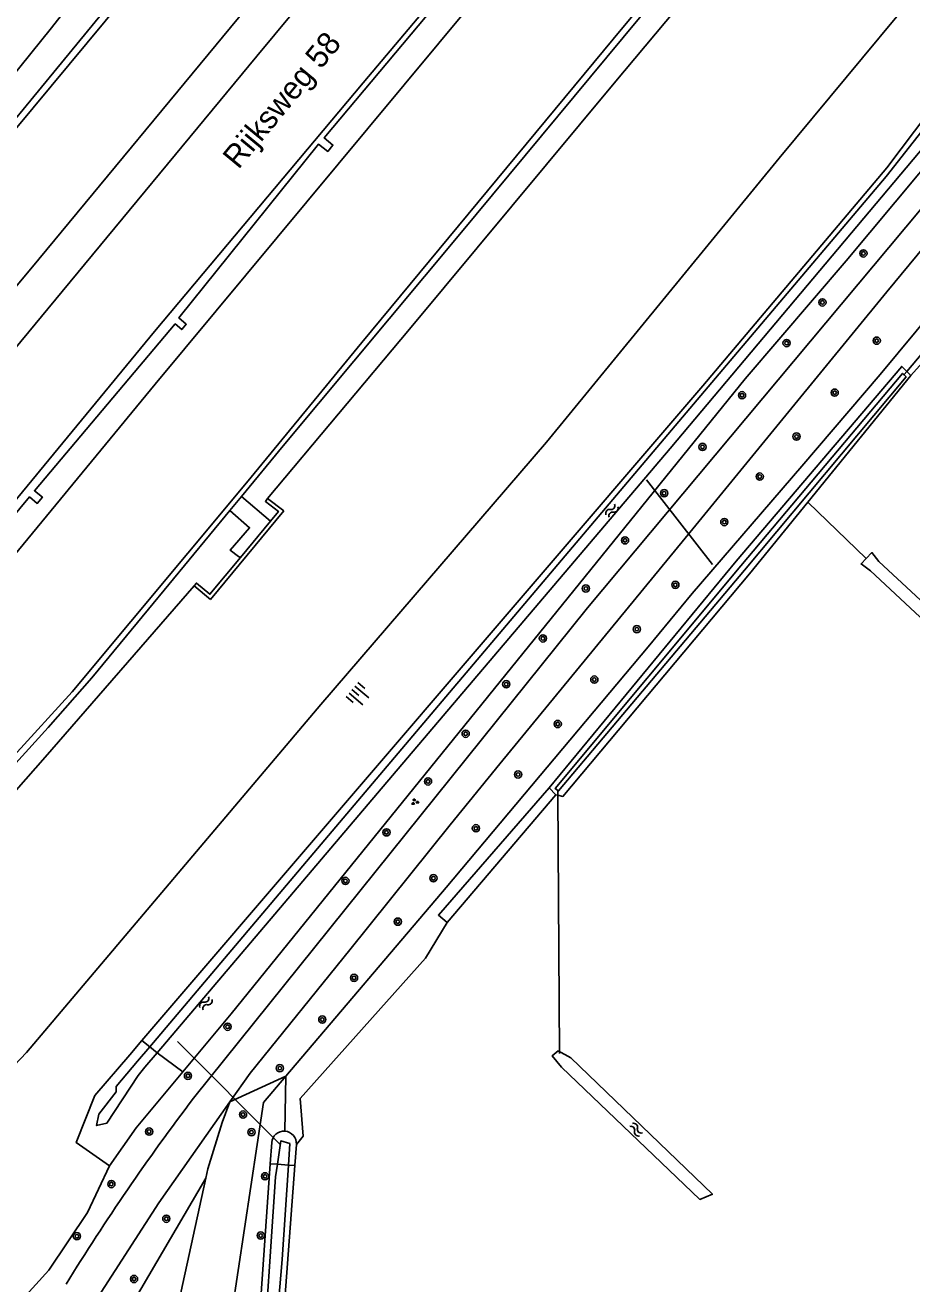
# Model space of a CAD drawing. Extents: x 135990 to 139000, y 393500 to 396000.
# Drawn here: x 136414.3 to 136512.1, y 395330 to 395468.8 of the extents above; entities that cross this region are included whole.
import ezdxf

# ---------------------------------------------------------------- set-up
doc = ezdxf.new("R2010")
doc.units = 0
for name, color, linetype in [('gg-anno-openbare ruimte label', 7, 'Continuous'), ('gg-knt-BGT kruinlijn', 7, 'Continuous'), ('gg-knt-bovenkant onderkant talud', 7, 'Continuous'), ('gg-knt-verharding', 7, 'Continuous'), ('gg-kntw-bovenkant insteek waterloop', 7, 'Continuous'), ('gg-kntw-greppel-droge sloot', 7, 'Continuous'), ('gg-kntw-waterlijn', 7, 'Continuous'), ('gg-kwrk-duiker nz buis', 7, 'Continuous'), ('gt-grn-groengrens', 7, 'Continuous'), ('gt-symb-boom', 7, 'Continuous'), ('gt-symb-groenvak', 7, 'Continuous'), ('gt-symb-talud symbool', 7, 'Continuous'), ('gt-symb-watersymbool', 7, 'Continuous'), ('gx-grn-maaiveld', 7, 'Continuous')]:
    doc.layers.add(name, color=color, linetype=linetype)

# ---------------------------------------------------------------- blocks, each defined once
blk = doc.blocks.new('gt0-BOOM')
at = {"layer": 'gt-symb-boom'}
for radius in [0.4, 0.2]:
    blk.add_circle((0, 0), radius, dxfattribs=at)
blk = doc.blocks.new('gt0-WA')
at = {"layer": 'gt-symb-watersymbool'}
for centre, start, end in [((-0.32, 0.02), 28.0725, 151.9275), ((0.43, 0.42), 208.0725, 331.9275), ((-0.32, -0.43), 28.0725, 151.9275), ((0.43, -0.03), 208.0725, 331.9275)]:
    blk.add_arc(centre, 0.425, start, end, dxfattribs=at)
blk = doc.blocks.new('gt0-GRVAK')
at = {"layer": 'gt-symb-groenvak'}
for p, q in [((-0.11, 0.19), (-0.23, 0.24)), ((-0.18, 0.15), (0.09, 0.15)), ((-0.09, 0.21), (-0.16, 0.32)), ((-0.05, 0.21), (-0.05, 0.39)), ((0, 0.21), (0.06, 0.32)), ((0.01, 0.19), (0.13, 0.24)), ((0.26, -0.05), (0.2, 0.06)), ((0.3, -0.05), (0.3, 0.13)), ((0.35, -0.05), (0.41, 0.06)), ((-0.25, -0.23), (-0.36, -0.18)), ((-0.32, -0.26), (-0.05, -0.26)), ((-0.23, -0.21), (-0.29, -0.09)), ((-0.18, -0.2), (-0.18, -0.02)), ((-0.14, -0.21), (-0.07, -0.09)), ((-0.12, -0.23), (0, -0.18)), ((0.24, -0.07), (0.12, -0.02)), ((0.17, -0.11), (0.44, -0.11)), ((0.37, -0.07), (0.49, -0.02))]:
    blk.add_line(p, q, dxfattribs=at)
blk = doc.blocks.new('gt0-TALUD_1')
at = {"layer": 'gt-symb-talud symbool'}
for p, q in [((-1, -1), (-1, 0)), ((-0.5, -2), (-0.5, 0)), ((0, -1), (0, 0)), ((0.5, -2), (0.5, 0)), ((1, -1), (1, 0))]:
    blk.add_line(p, q, dxfattribs=at)

msp = doc.modelspace()

# ---------------------------------------------------------------- linework, layer by layer
at = {"layer": 'gg-knt-BGT kruinlijn'}
for p, q in [((136503.696, 395491.543), (136479.304, 395462.397)), ((136479.304, 395462.397), (136456.715, 395435.272)), ((136456.715, 395435.272), (136441.073, 395416.607)), ((136441.073, 395416.607), (136442.844, 395415.241)), ((136442.844, 395415.241), (136434.754, 395405.48)), ((136432.952, 395406.983), (136416.544, 395388.108)), ((136434.754, 395405.48), (136432.952, 395406.983)), ((136416.544, 395388.108), (136400.306, 395369.712)), ((136443.072, 395352.931), (136440.614, 395350.038)), ((136440.614, 395350.038), (136433.976, 395305.932))]:
    msp.add_line(p, q, dxfattribs=at)
at = {"layer": 'gg-knt-bovenkant onderkant talud'}
msp.add_line((136434.244, 395341.683), (136428.408, 395315.007), dxfattribs=at)
msp.add_lwpolyline([(136436.917, 395350.098), (136436.04, 395347.825), (136434.47, 395342.715), (136434.244, 395341.683)], dxfattribs=at)
at = {"layer": 'gg-knt-verharding'}
for p in [(136436.917, 395350.098), (136422.37, 395328.623)]:
    msp.add_line(p, (136429.069, 395338.98), dxfattribs=at)
for points in [[(136432.897, 395350.499), (136476.36, 395404.544), (136518.42, 395454.805), (136528.779, 395467.524)], [(136531.236, 395465.44), (136520.138, 395452.36), (136509.397, 395439.378), (136498.57, 395426.205), (136487.972, 395413.263), (136477.16, 395400.121), (136466.703, 395387.377), (136461.205, 395380.628), (136450.153, 395366.863), (136439.151, 395353.262), (136436.917, 395350.098)]]:
    msp.add_lwpolyline(points, dxfattribs=at)
msp.add_arc((136637.443, 395195.104), 256.879, 142.77575, 148.32444, dxfattribs=at)
at = {"layer": 'gg-kntw-bovenkant insteek waterloop'}
for p, q in [((136512.013, 395430.157), (136500.663, 395416.22)), ((136472.872, 395383.954), (136472.145, 395384.703))]:
    msp.add_line(p, q, dxfattribs=at)
for points in [[(136472.145, 395384.703), (136492.778, 395409.693), (136511.029, 395431.176), (136512.013, 395430.157)], [(136472.872, 395383.954), (136473.098, 395383.898), (136473.64, 395383.764), (136494.218, 395408.307), (136500.663, 395416.22)], [(136508.483, 395409.645), (136507.734, 395410.651), (136507.12, 395410.006)], [(136507.12, 395410.006), (136506.545, 395409.402), (136507.571, 395408.62)], [(136507.571, 395408.62), (136548.649, 395370.333), (136567.969, 395352.327), (136568.845, 395353.696), (136549.789, 395371.359), (136508.483, 395409.645)], [(136473.111, 395355.712), (136472.45, 395355.169), (136473.501, 395353.925), (136488.77, 395339.339), (136490.137, 395339.909), (136474.526, 395354.95), (136473.111, 395355.712)]]:
    msp.add_lwpolyline(points, dxfattribs=at)
for start, end in [(85.86081, 175.97395), (355.72663, 85.85649)]:
    msp.add_arc((136442.886, 395345.51), 1.361, start, end, dxfattribs=at)
at = {"layer": 'gg-kntw-greppel-droge sloot'}
msp.add_line((136460.881, 395369.855), (136472.872, 395383.954), dxfattribs=at)
msp.add_lwpolyline([(136460.881, 395369.855), (136459.915, 395370.694), (136472.145, 395384.703)], dxfattribs=at)
at = {"layer": 'gg-kntw-waterlijn'}
for points in [[(136511.278, 395430.243), (136511.115, 395430.395), (136493.282, 395409.169), (136472.792, 395384.652), (136473.095, 395384.433)], [(136473.095, 395384.433), (136473.175, 395384.378), (136493.69, 395408.72), (136511.497, 395430.037), (136511.278, 395430.243)]]:
    msp.add_lwpolyline(points, dxfattribs=at)
at = {"layer": 'gg-kwrk-duiker nz buis'}
for p, q in [((136511.581, 395430.605), (136517.166, 395437.276)), ((136511.294, 395430.262), (136511.581, 395430.605)), ((136482.865, 395418.682), (136490.142, 395409.348)), ((136507.12, 395410.006), (136500.663, 395416.22)), ((136431.133, 395356.736), (136442.461, 395345.386))]:
    msp.add_line(p, q, dxfattribs=at)
msp.add_lwpolyline([(136473.095, 395384.433), (136473.098, 395383.898), (136473.27, 395355.444)], dxfattribs=at)
at = {"layer": 'gt-grn-groengrens'}
for p, q in [((136436.917, 395350.098), (136443.072, 395352.931)), ((136443.072, 395352.931), (136442.984, 395346.868)), ((136415.989, 395310.53), (136434.244, 395341.683))]:
    msp.add_line(p, q, dxfattribs=at)
for points in [[(136443.072, 395352.931), (136460.753, 395373.742), (136483.038, 395400.246), (136487.916, 395406.146), (136500, 395420.158), (136508.637, 395430.278), (136516.59, 395439.837), (136523.061, 395447.625), (136530.443, 395456.028), (136536.917, 395463.395)], [(136423.636, 395343.037), (136421.183, 395337.909), (136416.93, 395331.564), (136411.566, 395325.637), (136408.151, 395325.29), (136403.501, 395326.559), (136393.19, 395334.663), (136388.311, 395339.434), (136384.447, 395345.251)]]:
    msp.add_lwpolyline(points, dxfattribs=at)
at = {"layer": 'gx-grn-maaiveld'}
for p, q in [((136521.429, 395482.923), (136497.509, 395454.131)), ((136512.013, 395430.157), (136517.903, 395436.746)), ((136438.179, 395416.83), (136436.907, 395415.287)), ((136441.396, 395414.121), (136438.179, 395416.83)), ((136441.396, 395414.121), (136438.065, 395410.103)), ((136427.209, 395356.86), (136425.87, 395355.298)), ((136428.069, 395356.181), (136426.721, 395354.589)), ((136427.209, 395356.86), (136428.069, 395356.181)), ((136428.898, 395355.513), (136428.069, 395356.181)), ((136428.898, 395355.513), (136427.536, 395353.91)), ((136431.712, 395353.397), (136428.898, 395355.513)), ((136431.712, 395353.397), (136430.256, 395351.646)), ((136441.363, 395343.268), (136441.528, 395345.606)), ((136443.361, 395343.138), (136443.517, 395345.526)), ((136444.243, 395345.409), (136444.071, 395343.092)), ((136438.109, 395297.309), (136441.363, 395343.268)), ((136441.363, 395343.268), (136442.149, 395343.217)), ((136444.071, 395343.092), (136441.819, 395312.786)), ((136443.361, 395343.138), (136442.149, 395343.217)), ((136444.071, 395343.092), (136443.361, 395343.138))]:
    msp.add_line(p, q, dxfattribs=at)
for points in [[(136507.377, 395608.837), (136505.347, 395604.787), (136498.063, 395590.743), (136486.099, 395569.254), (136476.552, 395553.471), (136474.024, 395549.293), (136463.031, 395531.925), (136452.26, 395515.733), (136440.034, 395498.421), (136429.628, 395484.333), (136417.226, 395468.488), (136404.444, 395452.65), (136385.404, 395429.718), (136367.739, 395408.344)], [(136536.509, 395589.374), (136532.194, 395584.018), (136509.742, 395556.579), (136494.7, 395538.355), (136489.07, 395531.535), (136474.395, 395513.676), (136457.565, 395493.395), (136437.862, 395469.584), (136415.847, 395442.993), (136393.848, 395416.601), (136373.597, 395392.407)], [(136375.298, 395387.78), (136392.103, 395407.69), (136416.809, 395437.524), (136439.892, 395465.357), (136462.782, 395492.973), (136484.545, 395519.216), (136498.073, 395535.545), (136503.802, 395542.458), (136521.467, 395563.936), (136540.15, 395586.942)], [(136379.615, 395376.034), (136402.841, 395403.816), (136428.595, 395435.008), (136451.622, 395462.435), (136470.266, 395484.544), (136488.303, 395506.282), (136504.935, 395526.398), (136515.484, 395539.226), (136538.365, 395567.037), (136549.254, 395580.86)], [(136381.05, 395372.132), (136402.065, 395396.983), (136428.665, 395429.199), (136452.118, 395457.392), (136471.783, 395481.049), (136496.711, 395511.122), (136508.951, 395525.721), (136509.319, 395526.178), (136522.849, 395542.975), (136535.834, 395559.66), (136548.739, 395576.067), (136551.33, 395579.473)], [(136386.299, 395357.849), (136393.732, 395367.087), (136419.523, 395395.306), (136438.738, 395418.347), (136451.468, 395433.806), (136480.258, 395468.524), (136502.804, 395495.407), (136505.964, 395499.125), (136520.609, 395515.577), (136532.665, 395528.666), (136534.813, 395530.927)], [(136534.813, 395530.927), (136535.459, 395530.31), (136530.395, 395525.33), (136521.7, 395515.865), (136516.949, 395510.695), (136502.578, 395494.258), (136489.322, 395478.282), (136462.294, 395445.739), (136442.779, 395422.405), (136438.179, 395416.83)], [(136447.653, 395498.795), (136447.042, 395499.282), (136441.794, 395492.819), (136440.879, 395493.573), (136440.358, 395492.941), (136441.167, 395492.274), (136423.509, 395470.863), (136422.631, 395471.585), (136422.054, 395470.884), (136422.907, 395470.182), (136404.449, 395447.768), (136403.524, 395448.525), (136403.04, 395447.934), (136403.906, 395447.225), (136383.972, 395422.868), (136383.079, 395423.621), (136382.658, 395423.121), (136383.548, 395422.371), (136370.672, 395407.101), (136369.266, 395405.307)], [(136369.252, 395404.228), (136381.064, 395418.497), (136403.077, 395445.131), (136425.129, 395471.637), (136447.653, 395498.795)], [(136527.442, 395475.643), (136526.08, 395474.11), (136517.08, 395463.235), (136509.39, 395453.074), (136489.07, 395429.023), (136427.209, 395356.86)], [(136428.069, 395356.181), (136446.18, 395377.559), (136509.32, 395452.093), (136515.278, 395459.658), (136528.315, 395474.875)], [(136529.201, 395474.097), (136513.651, 395455.611), (136485.473, 395422.115), (136453.2, 395384.123), (136428.898, 395355.513)], [(136380.225, 395375.198), (136392.546, 395390.098), (136393.466, 395389.326), (136393.919, 395389.866), (136393.038, 395390.606), (136414.805, 395416.787), (136415.663, 395416.074), (136416.219, 395416.743), (136415.351, 395417.465), (136430.879, 395435.851), (136431.607, 395435.236), (136432.099, 395435.82), (136431.285, 395436.507), (136446.697, 395455.675), (136447.708, 395454.862), (136448.28, 395455.573), (136447.312, 395456.351), (136462.094, 395474.008)], [(136530.246, 395473.036), (136528.95, 395471.61), (136504.9, 395442.813), (136493.77, 395429.815), (136437.04, 395359.805), (136431.712, 395353.397)], [(136390.757, 395342.644), (136396.187, 395342.922), (136400.97, 395344.616), (136406.92, 395347.646), (136414.481, 395355.542), (136446.935, 395393.905), (136471.823, 395422.804), (136497.509, 395454.131)], [(136441.396, 395414.121), (136442.271, 395415.177), (136440.828, 395416.29), (136441.073, 395416.607)], [(136436.907, 395415.287), (136427.926, 395404.401), (136421.674, 395396.832), (136416.852, 395391.369), (136406.806, 395380.345), (136398.928, 395371.77), (136394.07, 395366.467), (136388.878, 395360.037)], [(136436.907, 395415.287), (136439.081, 395413.389), (136436.955, 395410.896), (136437.866, 395410.224), (136438.065, 395410.103)], [(136438.065, 395410.103), (136434.702, 395406.044), (136433.208, 395407.29), (136432.952, 395406.983)], [(136460.881, 395369.855), (136458.472, 395365.934), (136444.663, 395350.479), (136444.983, 395346.327), (136444.243, 395345.409)], [(136423.636, 395343.037), (136419.94, 395345.635), (136422, 395350.784), (136425.87, 395355.298)], [(136427.536, 395353.91), (136426.782, 395353.022), (136423.334, 395347.766), (136422.194, 395347.488), (136422.445, 395348.739), (136424.363, 395351.187), (136424.348, 395351.788), (136426.721, 395354.589)], [(136430.256, 395351.646), (136426.58, 395347.224), (136423.636, 395343.037)], [(136442.149, 395343.217), (136442.528, 395345.791), (136443.517, 395345.526)], [(136442.149, 395343.217), (136441.946, 395341.836), (136438.908, 395296.843)], [(136443.361, 395343.138), (136442.683, 395332.731), (136440.974, 395312.923), (136439.829, 395296.306)]]:
    msp.add_lwpolyline(points, dxfattribs=at)

# ---------------------------------------------------------------- block references
at = {"layer": 'gt-symb-boom'}
for p in [(136506.8, 395443.625), (136502.273, 395438.223), (136498.322, 395433.743), (136508.266, 395434.005), (136493.407, 395427.989), (136503.629, 395428.276), (136499.419, 395423.437), (136489.048, 395422.291), (136495.362, 395419.025), (136484.812, 395417.191), (136491.451, 395414.011), (136480.498, 395411.993), (136486.052, 395407.088), (136476.183, 395406.689), (136481.803, 395402.203), (136471.441, 395401.186), (136467.397, 395396.137), (136477.113, 395396.644), (136462.919, 395390.679), (136473.076, 395391.75), (136458.765, 395385.422), (136468.701, 395386.184), (136454.18, 395379.806), (136464.053, 395380.255), (136449.653, 395374.454), (136459.362, 395374.751), (136455.433, 395369.961), (136450.602, 395363.768), (136447.104, 395359.172), (136436.655, 395358.38), (136432.286, 395352.97), (136442.418, 395353.814), (136438.359, 395348.696), (136428.001, 395346.82), (136439.289, 395346.758), (136440.789, 395341.893), (136423.832, 395341.035), (136429.895, 395337.217), (136420.033, 395335.292), (136440.309, 395335.364), (136426.332, 395330.572)]:
    msp.add_blockref('gt0-BOOM', p, dxfattribs=at)
at = {"layer": 'gt-symb-groenvak'}
msp.add_blockref('gt0-GRVAK', (136457.302, 395383.161), dxfattribs=at)
at = {"layer": 'gt-symb-talud symbool', "xscale": 1.0004803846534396, "yscale": 1.0004803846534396, "rotation": 50.23109115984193}
msp.add_blockref('gt0-TALUD_1', (136450.369, 395395.54), dxfattribs=at)
at = {"layer": 'gt-symb-watersymbool'}
for p, rotation in [((136479.009, 395415.214), 50.19442890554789), ((136434.217, 395360.911), 50.19442890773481), ((136481.676, 395347.075), -43.7035699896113)]:
    msp.add_blockref('gt0-WA', p, dxfattribs=dict(at, rotation=rotation))

# ---------------------------------------------------------------- texts
at = {"layer": 'gg-anno-openbare ruimte label'}
msp.add_text('Rijksweg 58', height=2.5, rotation=50.5, dxfattribs=at).set_placement((136437.852, 395452.806))

doc.saveas('drawing.dxf')
